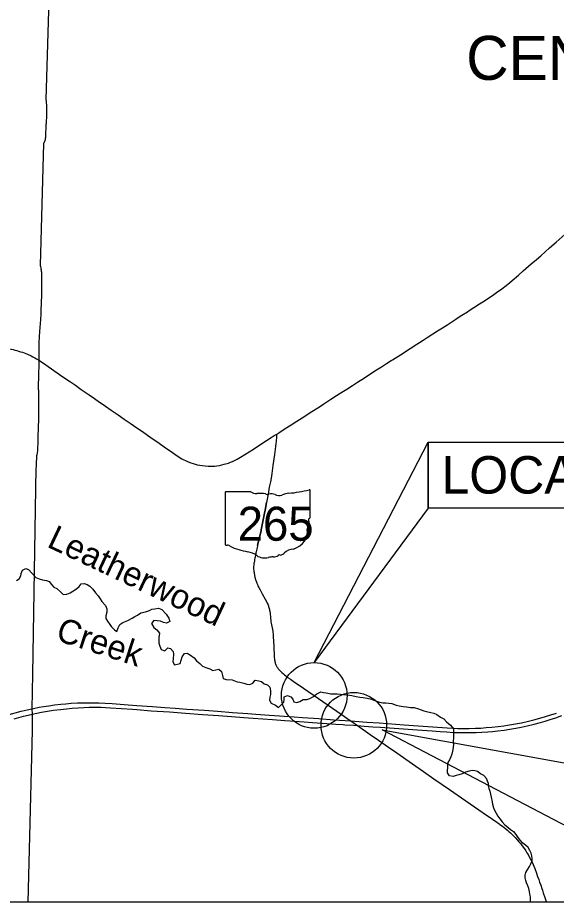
# Model space of a CAD drawing. Extents: x -29.6 to 34, y 0 to 22.
# Drawn here: x 7.023 to 9.469, y 13.504 to 17.521 of the extents above; entities that cross this region are included whole.
import ezdxf

# ---------------------------------------------------------------- set-up
doc = ezdxf.new("R2010")
doc.units = 0
for name, color, linetype in [('BR_P_Gen_Text', 7, 'Continuous'), ('Default', 7, 'Continuous'), ('GM_X_Interstate_Route', 7, 'Continuous'), ('GM_X_Major_Lake_Text', 7, 'Continuous'), ('GM_X_Minor_River', 7, 'Continuous'), ('GM_X_State_Route', 7, 'Continuous'), ('GM_X_State_Shield', 7, 'Continuous'), ('GM_X_Township', 7, 'Continuous'), ('GM_X_Township_Road', 7, 'Continuous'), ('GM_X_Township_Text', 7, 'Continuous'), ('GM_X_US_Route', 7, 'Continuous'), ('SH_Text', 7, 'Continuous')]:
    doc.layers.add(name, color=color, linetype=linetype)

msp = doc.modelspace()

# ---------------------------------------------------------------- linework, layer by layer
at = {"layer": 'BR_P_Gen_Text'}
for points in [[(8.8867, 15.5934), (8.8867, 15.2932), (8.3697, 14.5924)], [(8.8867, 15.5934), (10.432, 15.5934), (10.432, 15.2932), (8.8867, 15.2932)], [(9.5545, 14.1288), (9.5545, 13.8286), (8.6785, 14.2873)]]:
    msp.add_lwpolyline(points, close=True, dxfattribs=at)
at = {"layer": 'Default'}
for centre in [(8.3697, 14.4434), (8.5495, 14.3079)]:
    msp.add_circle(centre, 0.149, dxfattribs=at)
at = {"layer": 'GM_X_Interstate_Route'}
for points in [[(6.9729, 14.3544), (7.0392, 14.3713), (7.0653, 14.3776), (7.0878, 14.3826), (7.0945, 14.3841), (7.1208, 14.3896), (7.1408, 14.3933), (7.1638, 14.3969), (7.1897, 14.4004), (7.2186, 14.4036), (7.2411, 14.4057), (7.2665, 14.4076), (7.2941, 14.4091), (7.3173, 14.4099), (7.3384, 14.4102), (7.361, 14.4101), (7.3915, 14.4093), (7.4206, 14.4081), (7.4518, 14.4063), (7.5251, 14.401), (7.564, 14.3981)], [(7.0063, 14.3378), (7.0493, 14.3488), (7.084, 14.3572), (7.0883, 14.3581), (7.1103, 14.3629), (7.1303, 14.3669), (7.1576, 14.3717), (7.1857, 14.376), (7.2174, 14.3802), (7.2442, 14.3832), (7.2703, 14.3855), (7.298, 14.3875), (7.3234, 14.3888), (7.3482, 14.3895), (7.3751, 14.3898), (7.4014, 14.3894), (7.4217, 14.3886), (7.445, 14.3874), (7.5445, 14.3804), (7.564, 14.379)], [(7.564, 14.3981), (7.6347, 14.3929), (7.6906, 14.3888), (7.7378, 14.3854), (7.7915, 14.3815), (7.8707, 14.3759), (7.931, 14.3716), (7.9985, 14.3666), (8.0675, 14.3615), (8.1045, 14.3589), (8.167, 14.3544), (8.2781, 14.3464), (8.3166, 14.3436), (8.3899, 14.3384), (8.4582, 14.3333), (8.5355, 14.3278), (8.6093, 14.3227), (8.6645, 14.3187), (8.7785, 14.3106), (8.8417, 14.3058), (8.9085, 14.301), (8.9731, 14.2964), (9.003, 14.2947), (9.0219, 14.294), (9.0459, 14.2936), (9.0729, 14.2937), (9.102, 14.2944), (9.1268, 14.2955), (9.1508, 14.2971), (9.1769, 14.2994), (9.2045, 14.3024), (9.2305, 14.3058), (9.2571, 14.3098), (9.2837, 14.3143), (9.3109, 14.3197), (9.3373, 14.3254), (9.3663, 14.3324), (9.3938, 14.3396), (9.4204, 14.3472), (9.4441, 14.3546), (9.4696, 14.3632)], [(7.564, 14.379), (7.6287, 14.3741), (7.7122, 14.3683), (7.7848, 14.363), (7.8625, 14.3574), (7.9351, 14.3523), (7.994, 14.3478), (8.0506, 14.3439), (8.0927, 14.3408), (8.1806, 14.3344), (8.2365, 14.3302), (8.2604, 14.3283), (8.3243, 14.3238), (8.3614, 14.3211), (8.4268, 14.3166), (8.4477, 14.3151)], [(9.0832, 14.2748), (9.1045, 14.2753), (9.1314, 14.2766), (9.1583, 14.2784), (9.18, 14.2802), (9.2039, 14.2828), (9.232, 14.2863), (9.2579, 14.2902), (9.2852, 14.2949), (9.3102, 14.2997), (9.3372, 14.3056), (9.369, 14.3132), (9.3972, 14.3206), (9.4189, 14.3267), (9.4419, 14.3337), (9.4674, 14.3421), (9.4942, 14.3516)], [(8.4477, 14.3151), (8.4674, 14.3136), (8.5005, 14.3112)], [(8.5005, 14.3112), (8.5088, 14.3106), (8.5495, 14.3079), (8.5657, 14.3067), (8.5967, 14.3045), (8.6356, 14.3016)], [(8.6356, 14.3016), (8.6686, 14.2992), (8.7754, 14.2914), (8.8603, 14.2854), (8.9046, 14.2821), (8.941, 14.2796)], [(8.941, 14.2796), (8.9715, 14.2774), (9.0013, 14.2758), (9.0296, 14.2748), (9.0551, 14.2745), (9.082, 14.2747), (9.0832, 14.2748)]]:
    msp.add_lwpolyline(points, dxfattribs=at)
at = {"layer": 'GM_X_Minor_River'}
for points in [[(7.0175, 14.9648), (7.0299, 14.9724), (7.0373, 14.9858), (7.039, 14.9969), (7.0442, 15.0116), (7.0592, 15.0201), (7.0717, 15.0153), (7.0868, 14.999), (7.1051, 14.9796), (7.1207, 14.973), (7.1362, 14.9687), (7.1539, 14.9653), (7.1655, 14.9609), (7.1766, 14.9472), (7.1874, 14.9349), (7.2002, 14.9292), (7.2167, 14.9142), (7.2292, 14.9014), (7.246, 14.9038), (7.2611, 14.9097), (7.2897, 14.9272), (7.3016, 14.9379), (7.3108, 14.9495), (7.3246, 14.951), (7.3379, 14.9471), (7.3499, 14.9396), (7.3637, 14.9255), (7.3767, 14.9087), (7.3878, 14.8964), (7.3972, 14.8827), (7.4053, 14.8698), (7.4222, 14.8518), (7.4272, 14.8367), (7.4277, 14.822), (7.4239, 14.8051), (7.4239, 14.7923), (7.4307, 14.7803), (7.4418, 14.7662), (7.4494, 14.7547), (7.4619, 14.7415), (7.4735, 14.7331), (7.4791, 14.7509), (7.4875, 14.7652), (7.5011, 14.7746), (7.5228, 14.7832), (7.5422, 14.7944), (7.5545, 14.8021), (7.564, 14.8069)], [(7.564, 14.8069), (7.5669, 14.8084), (7.5819, 14.8187), (7.6036, 14.8224), (7.6208, 14.8292), (7.6323, 14.835), (7.6451, 14.8365), (7.6628, 14.8401), (7.6774, 14.8336), (7.6966, 14.8124), (7.7087, 14.7943), (7.7132, 14.7797), (7.6987, 14.772), (7.6858, 14.775), (7.6712, 14.7811), (7.6565, 14.7828), (7.641, 14.7832), (7.6305, 14.7698), (7.6408, 14.7525), (7.6555, 14.742), (7.6662, 14.7261), (7.6641, 14.7069), (7.6633, 14.6932), (7.6643, 14.6812), (7.6679, 14.6666), (7.6738, 14.6515), (7.6907, 14.6459), (7.7047, 14.6597), (7.7172, 14.6558), (7.7292, 14.643), (7.7302, 14.6302), (7.729, 14.6097), (7.7278, 14.5955), (7.7358, 14.5822), (7.761, 14.5882), (7.7658, 14.6038), (7.7701, 14.6189), (7.7811, 14.6332), (7.7926, 14.6346)], [(7.7926, 14.6346), (7.8073, 14.6267), (7.8251, 14.6135), (7.8353, 14.6012), (7.8496, 14.5884), (7.8621, 14.5769), (7.8776, 14.5708), (7.8949, 14.5647), (7.9096, 14.5573), (7.9366, 14.5628), (7.9491, 14.5518), (7.9527, 14.5345), (7.9564, 14.5203), (7.9692, 14.516), (7.9967, 14.5148), (8.0198, 14.5057), (8.0322, 14.5031), (8.0495, 14.4992), (8.0633, 14.494), (8.0779, 14.4936), (8.0902, 14.4995), (8.1017, 14.5125), (8.1181, 14.5095), (8.1305, 14.5065), (8.143, 14.4959), (8.1567, 14.4911), (8.1679, 14.481), (8.1715, 14.4637), (8.1703, 14.4477), (8.1677, 14.4361), (8.1665, 14.4223), (8.1746, 14.4086), (8.1937, 14.3995), (8.2079, 14.3893), (8.2321, 14.4122), (8.2334, 14.425), (8.2324, 14.4366), (8.2483, 14.4434), (8.2629, 14.4377), (8.2719, 14.4262), (8.2777, 14.4147), (8.2906, 14.4117), (8.3038, 14.4162), (8.3188, 14.4252), (8.3357, 14.4249), (8.3498, 14.429), (8.3661, 14.4393), (8.3811, 14.4505), (8.4001, 14.4595), (8.4116, 14.4574), (8.4232, 14.4548), (8.4453, 14.4501), (8.4591, 14.4502), (8.4737, 14.4507), (8.4892, 14.4499), (8.5295, 14.4445), (8.541, 14.4428), (8.5597, 14.438), (8.577, 14.4355), (8.5916, 14.4342), (8.6102, 14.4313), (8.6302, 14.4265), (8.6475, 14.4191), (8.6666, 14.4126), (8.6808, 14.4105), (8.6954, 14.4092), (8.7087, 14.408), (8.7215, 14.4063), (8.7424, 14.3998), (8.7553, 14.3959), (8.773, 14.3929), (8.7894, 14.3912), (8.8071, 14.3892), (8.8231, 14.3879), (8.8435, 14.3823), (8.867, 14.3736), (8.8795, 14.3701), (8.8994, 14.3663), (8.9132, 14.3624), (8.9269, 14.3567), (8.943, 14.3453), (8.9585, 14.3374), (8.9706, 14.3233), (8.9888, 14.3079), (9.0018, 14.2911), (9.0028, 14.2786), (9.0024, 14.2631), (9.0021, 14.2498), (9.0008, 14.2378), (9.0014, 14.2236), (9.0001, 14.2067), (8.9976, 14.1907), (8.9941, 14.1769), (8.9898, 14.1649), (8.9837, 14.1506), (8.9771, 14.139), (8.975, 14.1266), (8.9742, 14.1093), (8.975, 14.109)], [(9.1593, 14.0467), (9.1517, 14.067), (9.1392, 14.0798), (9.1254, 14.0881), (9.1112, 14.0974), (9.0992, 14.1013), (9.0872, 14.1021), (9.0735, 14.0998), (9.0567, 14.0952), (9.0408, 14.0875), (9.0267, 14.083), (9.0138, 14.0798), (9.0001, 14.0757), (8.9837, 14.0778), (8.9752, 14.092), (8.9742, 14.1093)], [(9.1593, 14.0467), (9.1589, 14.0329), (9.1626, 14.0201), (9.1676, 14.0086), (9.1703, 13.9944), (9.1731, 13.9816), (9.1773, 13.9608), (9.18, 13.9492), (9.1842, 13.9337), (9.1896, 13.92), (9.1963, 13.9081), (9.2035, 13.8953), (9.2121, 13.883), (9.2237, 13.8698), (9.2349, 13.8566), (9.2483, 13.8456), (9.2608, 13.8347), (9.2741, 13.8255), (9.2845, 13.8114), (9.2947, 13.7986), (9.3051, 13.7854), (9.314, 13.7748)], [(9.3545, 13.7275), (9.3486, 13.7398), (9.341, 13.7531), (9.3298, 13.7636), (9.3117, 13.7775)], [(9.3524, 13.5041), (9.3523, 13.5169), (9.3513, 13.5293), (9.3485, 13.5408), (9.3466, 13.5537), (9.3438, 13.5665), (9.3401, 13.5794), (9.3333, 13.5922), (9.3301, 13.6037), (9.3282, 13.6157), (9.3276, 13.6276), (9.3306, 13.6392), (9.3398, 13.6544), (9.3467, 13.667), (9.3537, 13.6786), (9.3589, 13.692), (9.3588, 13.7031), (9.3582, 13.7155), (9.3545, 13.7275)]]:
    msp.add_lwpolyline(points, dxfattribs=at)
at = {"layer": 'GM_X_State_Route'}
for points in [[(8.1991, 15.6303), (8.1987, 15.6248), (8.1977, 15.6117), (8.197, 15.6032), (8.1965, 15.5967), (8.1952, 15.5872), (8.1934, 15.5744), (8.1887, 15.5376), (8.1816, 15.4871), (8.1765, 15.4511), (8.1734, 15.4302), (8.1704, 15.4137), (8.1657, 15.3895), (8.1597, 15.3573), (8.1526, 15.3192)], [(8.1526, 15.3192), (8.1512, 15.3114), (8.1476, 15.2921), (8.1422, 15.2628), (8.1382, 15.2413), (8.1291, 15.195), (8.1282, 15.1908), (8.1271, 15.1859), (8.1253, 15.1783), (8.1202, 15.1564), (8.1123, 15.1235)], [(8.1123, 15.1235), (8.1119, 15.1218), (8.1089, 15.1091), (8.1046, 15.0893), (8.101, 15.0715), (8.1001, 15.0665), (8.0989, 15.0608), (8.0978, 15.0543), (8.0964, 15.0472), (8.0956, 15.0421), (8.0947, 15.0356), (8.0941, 15.029), (8.094, 15.0257), (8.0939, 15.0224), (8.0941, 15.0197), (8.0942, 15.0173), (8.0948, 15.0114), (8.0953, 15.0068), (8.0962, 15.0013), (8.0985, 14.9883), (8.1005, 14.9798), (8.1036, 14.9693), (8.1073, 14.9582), (8.1093, 14.9526), (8.1115, 14.9472), (8.1142, 14.941), (8.1176, 14.934), (8.1234, 14.923), (8.1337, 14.9045), (8.147, 14.8811), (8.1532, 14.8696), (8.1566, 14.8624), (8.16, 14.8544), (8.1614, 14.8509), (8.1625, 14.8476), (8.1637, 14.8434), (8.1649, 14.8388), (8.1659, 14.8341), (8.1669, 14.8292), (8.1679, 14.8238), (8.1689, 14.8173), (8.1698, 14.81), (8.1705, 14.8028), (8.1715, 14.7926), (8.1722, 14.7857), (8.1731, 14.7783), (8.174, 14.7711), (8.1752, 14.7645), (8.1781, 14.7504), (8.1797, 14.7426), (8.181, 14.7359), (8.1821, 14.7295), (8.1827, 14.7233), (8.1838, 14.711), (8.1851, 14.6885), (8.1861, 14.6689), (8.1868, 14.65), (8.1874, 14.6362), (8.1879, 14.6246), (8.1883, 14.6166), (8.1889, 14.6085), (8.1894, 14.6045), (8.1901, 14.6005), (8.1909, 14.597), (8.1918, 14.5934), (8.1929, 14.5899), (8.1942, 14.5864), (8.1956, 14.5831), (8.1971, 14.5797), (8.1987, 14.5764), (8.2005, 14.5732), (8.2021, 14.5704), (8.2042, 14.5674), (8.2063, 14.5644), (8.2088, 14.5613), (8.2143, 14.5553), (8.2222, 14.5477), (8.2294, 14.5414), (8.2345, 14.5373), (8.2408, 14.5323), (8.2449, 14.5292), (8.2519, 14.524), (8.2621, 14.5169), (8.2805, 14.504), (8.3011, 14.4901), (8.3409, 14.4632), (8.3697, 14.4434), (8.428, 14.4025), (8.4962, 14.3551), (8.5288, 14.3324)], [(8.5288, 14.3324), (8.5355, 14.3278), (8.5657, 14.3067), (8.6241, 14.2662), (8.6611, 14.2402), (8.7077, 14.2078), (8.7449, 14.1822), (8.8161, 14.1328), (8.8657, 14.0983), (8.9134, 14.0649), (8.9841, 14.0161), (9.0577, 13.9651), (9.1177, 13.9238), (9.1526, 13.8996), (9.1681, 13.8889), (9.1728, 13.8857), (9.1856, 13.8768), (9.1923, 13.8723), (9.2096, 13.8602), (9.2131, 13.8577), (9.2244, 13.8496), (9.232, 13.8439), (9.24, 13.8376), (9.2484, 13.8305), (9.2538, 13.8256), (9.2603, 13.8198), (9.2713, 13.8092), (9.2749, 13.8056), (9.2825, 13.7977), (9.2933, 13.7858), (9.2996, 13.7787), (9.3075, 13.7691), (9.3146, 13.7599), (9.3241, 13.7469), (9.3306, 13.7373), (9.3357, 13.7293), (9.3406, 13.7211), (9.3464, 13.711), (9.3525, 13.6994), (9.3574, 13.6896), (9.3605, 13.683), (9.3664, 13.6688), (9.3709, 13.6572), (9.3727, 13.6525), (9.3773, 13.6402), (9.384, 13.6217), (9.3891, 13.6074), (9.3934, 13.5957), (9.3985, 13.5813), (9.4032, 13.5675), (9.4059, 13.5592), (9.4098, 13.5475), (9.4172, 13.5254), (9.4218, 13.5116), (9.4243, 13.5041)]]:
    msp.add_lwpolyline(points, dxfattribs=at)
at = {"layer": 'GM_X_State_Shield'}
for p, q in [((7.9646, 15.3638), (7.9646, 15.1293)), ((8.0815, 15.3679), (7.9684, 15.3679)), ((8.3508, 15.251), (8.3508, 15.3737)), ((8.3507, 15.251), (8.3508, 15.251))]:
    msp.add_line(p, q, dxfattribs=at)
for centre, major_axis, start_param, end_param in [((7.969, 15.3643), (0.00447, 0), 1.712693, 3.28349), ((8.1084, 15.3951), (0.0434, 0), 4.042523, 4.731795), ((8.1228, 15.2362), (0.1558, 0), 1.404758, 1.657858), ((8.1582, 15.3655), (0.0125, 0), 3.836095, 5.185415), ((8.1765, 15.3384), (0.026, 0), 0.950623, 2.079405), ((8.2101, 15.3756), (0.0313, 0), 4.081561, 5.145723), ((8.2654, 15.2962), (0.0824, 0), 1.699011, 2.107814), ((8.2132, 15.6876), (0.4096, 0), 4.814394, 5.042369), ((8.3465, 15.3742), (0.0043, 0), 6.141152, 7.989035), ((8.3498, 15.242), (0.00665, 0), 1.883978, 3.671073), ((8.3075, 15.2265), (0.0399, 0), 5.934695, 6.695948), ((8.3462, 15.2505), (0.0046, 0), 5.05454, 6.418171), ((8.2361, 15.1841), (0.1024, 0), 5.101752, 6.440018), ((8.3662, 15.1997), (0.0291, 0), 2.387724, 3.262537), ((7.969, 15.1288), (0.00451, 0), 3.00124, 4.508301), ((7.9697, 15.1528), (0.0344, 0), 4.665946, 4.897461), ((7.9768, 15.1158), (0.0124, 0), 0.519207, 1.627899), ((8.1336, 15.3265), (0.2958, 0), 4.195997, 4.488961), ((8.2793, 15.0635), (0.0561, 0), 1.647645, 2.488434), ((8.0454, 15.024), (0.0925, 0), 0.823519, 1.323587), ((8.1455, 15.1146), (0.0587, 0), 4.026481, 4.996735), ((8.1794, 15.0335), (0.0483, 0), 1.495662, 1.94098), ((8.1837, 15.0971), (0.0313, 0), 4.691044, 5.507374), ((8.212, 15.0743), (0.00881, 0), 1.147584, 2.315152), ((8.2083, 15.1066), (0.0331, 0), 4.937069, 5.64225)]:
    msp.add_ellipse(centre, major_axis=major_axis, ratio=0.8, start_param=start_param, end_param=end_param, dxfattribs=at)
at = {"layer": 'GM_X_Township'}
msp.add_lwpolyline([(7.1752, 17.958), (7.1502, 17.1493), (7.1516, 17.1414), (7.1525, 17.1345), (7.1534, 17.1254), (7.1536, 17.12), (7.1537, 17.1165), (7.1538, 17.108), (7.1539, 17.0951), (7.1539, 17.0873), (7.1537, 17.0796), (7.1533, 17.0688), (7.153, 17.0638), (7.1527, 17.0577), (7.1522, 17.0498), (7.1519, 17.0446), (7.1516, 17.0398), (7.1512, 17.0353), (7.1509, 17.0316), (7.1505, 17.0281), (7.15, 17.0152), (7.1495, 17.0024), (7.1493, 16.991), (7.1491, 16.9854), (7.149, 16.9827), (7.1486, 16.9769), (7.1482, 16.9716), (7.1474, 16.9665), (7.147, 16.9646), (7.1467, 16.9632), (7.1464, 16.9621), (7.1459, 16.9607), (7.1451, 16.959), (7.1437, 16.9563), (7.1411, 16.9513), (7.1403, 16.95), (7.1245, 16.3956), (7.1262, 16.3911), (7.1278, 16.385), (7.1282, 16.3831), (7.1285, 16.3811), (7.1293, 16.3755), (7.1295, 16.3737), (7.1302, 16.3676), (7.1303, 16.3662), (7.1304, 16.3648), (7.1311, 16.349), (7.1314, 16.3363), (7.1313, 16.3184), (7.1312, 16.2987), (7.1306, 16.2694), (7.1304, 16.2605), (7.128, 16.1919), (7.1273, 16.1742), (7.1262, 16.151), (7.1226, 16.0956), (7.121, 16.0717), (7.1195, 16.0451), (7.1194, 16.0429), (7.1193, 16.0326), (7.1192, 16.0276), (7.1192, 16.0072), (7.1193, 15.9927), (7.1192, 15.9891), (7.1191, 15.9837), (7.1188, 15.9752), (7.1189, 15.9658), (7.1193, 15.9559), (7.1193, 15.9549), (7.1194, 15.9532), (7.1193, 15.9515), (7.1187, 15.935), (7.1181, 15.9115), (7.1173, 15.8896), (7.1168, 15.8795), (7.1161, 15.8621), (7.1159, 15.8592), (7.116, 15.8541), (7.116, 15.8469), (7.1162, 15.8389), (7.1166, 15.8324), (7.1168, 15.8303), (7.1175, 15.8179), (7.1177, 15.8088), (7.1177, 15.8061), (7.1175, 15.8009), (7.1174, 15.7946), (7.1174, 15.7903), (7.1171, 15.7838), (7.117, 15.7758), (7.117, 15.7646), (7.1171, 15.7551), (7.1169, 15.7392), (7.1169, 15.721), (7.1168, 15.7093), (7.1168, 15.6977), (7.1167, 15.6867), (7.1165, 15.6704), (7.1158, 15.6515), (7.1146, 15.6247), (7.1141, 15.6043), (7.1137, 15.5854), (7.1133, 15.5707), (7.1128, 15.5602), (7.1123, 15.5541), (7.111, 15.5446), (7.1096, 15.536), (7.1086, 15.5313), (7.1083, 15.5297), (7.1081, 15.5277), (7.108, 15.5263), (7.108, 15.523), (7.1077, 15.5143), (7.1074, 15.507), (7.1072, 15.5022), (7.1069, 15.4945), (7.1064, 15.4868), (7.1062, 15.481), (7.1058, 15.4753), (7.0895, 14.5394), (7.0876, 14.3833), (7.088, 14.3587), (7.0879, 14.284), (7.0691, 13.5041)], dxfattribs=at)
at = {"layer": 'GM_X_Township_Road'}
msp.add_lwpolyline([(8.1123, 15.1235), (8.1202, 15.1564), (8.1253, 15.1783), (8.1271, 15.1859), (8.1282, 15.1908), (8.1291, 15.195), (8.1382, 15.2413), (8.1422, 15.2628), (8.1476, 15.2921), (8.1512, 15.3114), (8.1526, 15.3192)], dxfattribs=at)
at = {"layer": 'GM_X_US_Route'}
for points in [[(8.7247, 15.9673), (8.7609, 15.9899), (8.8049, 16.019), (8.8349, 16.0382), (8.8479, 16.0465), (8.8641, 16.0572), (8.8818, 16.0683), (8.9298, 16.0987), (8.9521, 16.1128), (8.976, 16.1284), (9.0127, 16.1521), (9.028, 16.1618), (9.0402, 16.1698), (9.0651, 16.1856), (9.0732, 16.191), (9.0948, 16.2046), (9.1206, 16.221), (9.1434, 16.2358), (9.1584, 16.2456), (9.1789, 16.2594), (9.198, 16.2729), (9.2213, 16.29), (9.2418, 16.3055), (9.2566, 16.3173), (9.2689, 16.3276), (9.2972, 16.3517), (9.3192, 16.3709), (9.3553, 16.4025), (9.3784, 16.4223), (9.3982, 16.4398), (9.4385, 16.4755), (9.4686, 16.5019), (9.5092, 16.5373)], [(6.9659, 16.0196), (6.968, 16.0194), (6.9762, 16.0183), (6.9846, 16.0169), (6.9939, 16.0151), (7.0018, 16.0135), (7.0099, 16.0117), (7.0188, 16.0092), (7.027, 16.0069), (7.0363, 16.004), (7.0441, 16.0015), (7.0529, 15.9983), (7.0601, 15.9955), (7.0671, 15.9925), (7.0836, 15.9848), (7.0923, 15.9806), (7.1005, 15.9761), (7.1088, 15.9714), (7.1192, 15.9651)], [(7.1192, 15.9651), (7.1308, 15.9577), (7.1501, 15.9447), (7.1866, 15.9195), (7.2279, 15.8908), (7.2621, 15.8673), (7.2849, 15.8516), (7.3111, 15.8332), (7.3473, 15.8084), (7.3717, 15.7916), (7.395, 15.7753), (7.4113, 15.7643), (7.422, 15.7568), (7.4476, 15.739), (7.4653, 15.7267), (7.4795, 15.7169), (7.5064, 15.6983), (7.534, 15.6793), (7.564, 15.6584)], [(8.1991, 15.6303), (8.213, 15.6389), (8.2383, 15.655), (8.2645, 15.6719), (8.2913, 15.6894), (8.3145, 15.7043), (8.3365, 15.7181), (8.3508, 15.7275), (8.3929, 15.7545), (8.4135, 15.7676), (8.4454, 15.7882), (8.4712, 15.805), (8.4945, 15.8199), (8.5176, 15.8347), (8.5436, 15.8511), (8.566, 15.8655), (8.5974, 15.8858), (8.6274, 15.9048), (8.6529, 15.9213), (8.6758, 15.9362), (8.6976, 15.95), (8.7194, 15.964), (8.7247, 15.9673)], [(7.564, 15.6584), (7.5668, 15.6565), (7.5957, 15.6368), (7.6226, 15.6181), (7.665, 15.5884), (7.6884, 15.5724), (7.703, 15.5622), (7.7147, 15.554), (7.7368, 15.5388), (7.7567, 15.5258), (7.7687, 15.5183), (7.7776, 15.5133), (7.7848, 15.5097), (7.7968, 15.5043), (7.8096, 15.4992), (7.8191, 15.4958), (7.8292, 15.4928), (7.8387, 15.4906), (7.8497, 15.4885), (7.8611, 15.4868), (7.8742, 15.4854), (7.8873, 15.4845), (7.898, 15.4842), (7.9064, 15.4843), (7.9183, 15.4851), (7.9278, 15.4861), (7.9394, 15.4879), (7.9501, 15.4901), (7.9608, 15.4928), (7.9796, 15.4986), (7.9893, 15.502), (7.9987, 15.5059), (8.0073, 15.51), (8.0196, 15.5163), (8.0342, 15.5246), (8.0541, 15.5367), (8.0938, 15.5623), (8.1231, 15.5811), (8.1534, 15.6011), (8.1748, 15.615), (8.1884, 15.6233), (8.1991, 15.6303)]]:
    msp.add_lwpolyline(points, dxfattribs=at)
at = {"layer": 'SH_Text'}
msp.add_line((20.8747, 13.5041), (2.5893, 13.5041), dxfattribs=at)

# ---------------------------------------------------------------- texts
at = {"layer": 'BR_P_Gen_Text'}
msp.add_text('LOCATION 10', height=0.17, dxfattribs=at).set_placement((8.9474, 15.36))
at = {"layer": 'GM_X_Major_Lake_Text'}
for s, height, rotation, p in [('Leatherwood', 0.110971, 334.7303, (7.1511, 15.1203)), ('Creek', 0.11097, 342.0368, (7.191, 14.6952))]:
    msp.add_text(s, height=height, rotation=rotation, dxfattribs=at).set_placement(p)
at = {"layer": 'GM_X_State_Shield'}
msp.add_text('265', height=0.1545, dxfattribs=at).set_placement((8.0221, 15.1459))
at = {"layer": 'GM_X_Township_Text'}
msp.add_text('CENTER', height=0.19975, rotation=0, dxfattribs=at).set_placement((9.0597, 17.2385))

doc.saveas('drawing.dxf')
